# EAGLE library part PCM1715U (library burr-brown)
Dual Voltage Output CMOS Delta-Sigma DAC
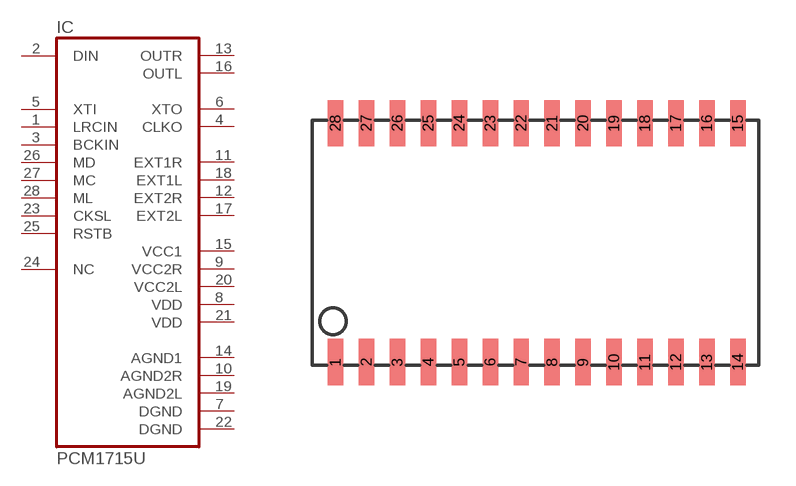
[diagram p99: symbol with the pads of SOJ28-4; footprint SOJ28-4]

Designator prefix IC

## PCM1715U (OC_FARNELL: unknown; OC_NEWARK: unknown)  [SOJ28-4]
1  LRCIN  in
2  DIN  in
3  BCKIN  in
4  CLKO  out
5  XTI  in
6  XTO  out
7  DGND  pwr
8  VDD  pwr
9  VCC2R  pwr
10  AGND2R  pwr
11  EXT1R  out
12  EXT2R  out
13  OUTR  out
14  AGND1  pwr
15  VCC1  pwr
16  OUTL  out
17  EXT2L  out
18  EXT1L  out
19  AGND2L  pwr
20  VCC2L  pwr
21  VDD  pwr
22  DGND  pwr
23  CKSL  in
24  NC  nc
25  RSTB  in
26  MD  in
27  MC  in
28  ML  in

## Footprint SOJ28-4 (pad centres in mm)
Small Outline J-Lead Package
smd 0.635 x 1.905: 1 -8.255,-4.902; 2 -6.985,-4.902; 3 -5.715,-4.902; 4 -4.445,-4.902; 5 -3.175,-4.902; 6 -1.905,-4.902; 7 -0.635,-4.902; 8 0.635,-4.902; 9 1.905,-4.902; 10 3.175,-4.902; 11 4.445,-4.902; 12 5.715,-4.902; 13 6.985,-4.902; 14 8.255,-4.902; 15 8.255,4.902; 16 6.985,4.902; 17 5.715,4.902; 18 4.445,4.902; 19 3.175,4.902; 20 1.905,4.902; 21 0.635,4.902; 22 -0.635,4.902; 23 -1.905,4.902; 24 -3.175,4.902; 25 -4.445,4.902; 26 -5.715,4.902; 27 -6.985,4.902; 28 -8.255,4.902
